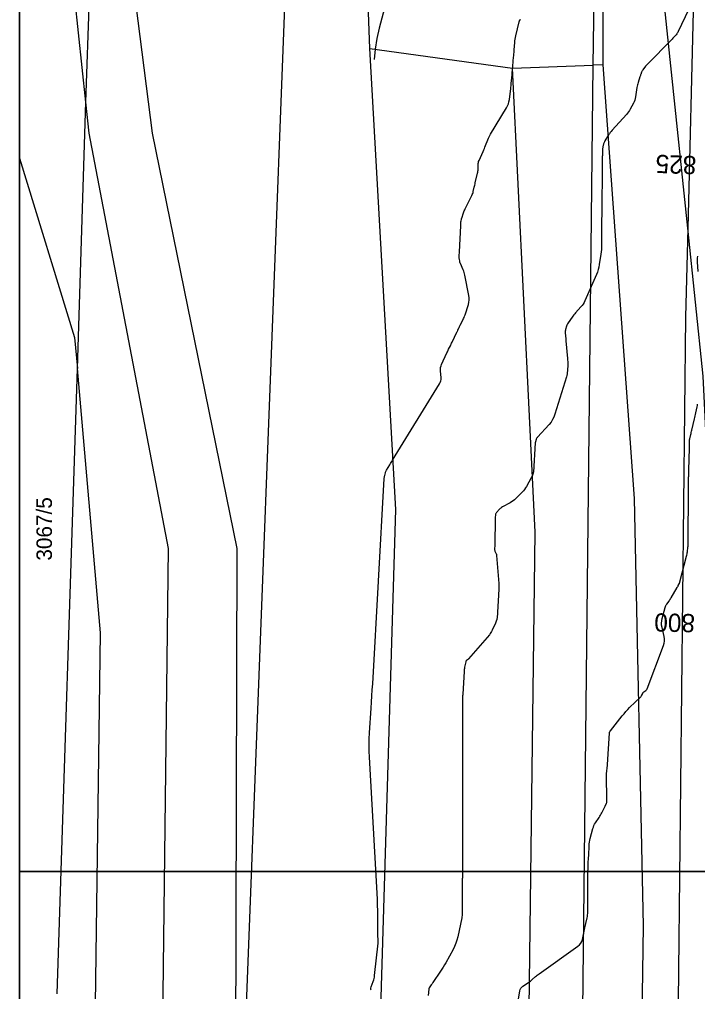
# Model space of a CAD drawing. Extents: x -534410 to -534262, y -1190162 to -1189584.
# Drawn here: x -534410.1 to -534373, y -1189801 to -1189747.8 of the extents above; entities that cross this region are included whole.
import ezdxf

# ---------------------------------------------------------------- set-up
doc = ezdxf.new("R2010")
doc.units = 0
for name, color, linetype in [('30', 7, 'Continuous'), ('31', 7, 'Continuous'), ('_N_text', 7, 'Continuous'), ('_rámeček', 7, 'Continuous'), ('_rámeček_mřížka', 7, 'Continuous'), ('Hranice parcel', 7, 'Continuous'), ('Parcelní čísla', 7, 'Continuous')]:
    doc.layers.add(name, color=color, linetype=linetype)

msp = doc.modelspace()

# ---------------------------------------------------------------- linework, layer by layer
at = {"layer": '30'}
for points in [[(-534389.675, -1189745.496), (-534390.401, -1189748.249), (-534390.532, -1189748.817), (-534390.627, -1189749.39), (-534390.685, -1189749.968)], [(-534373.458, -1189747.24), (-534374.015, -1189748.431), (-534374.04, -1189748.478), (-534374.067, -1189748.523), (-534374.097, -1189748.566), (-534374.131, -1189748.607), (-534374.272, -1189748.765), (-534374.307, -1189748.805), (-534374.343, -1189748.843), (-534374.38, -1189748.882), (-534374.417, -1189748.92), (-534375.669, -1189750.182), (-534375.706, -1189750.219), (-534375.741, -1189750.258), (-534375.775, -1189750.298), (-534375.807, -1189750.339), (-534375.958, -1189750.534), (-534375.978, -1189750.562), (-534375.995, -1189750.591), (-534376.01, -1189750.621), (-534376.023, -1189750.652), (-534376.068, -1189750.78), (-534376.08, -1189750.812), (-534376.091, -1189750.845), (-534376.102, -1189750.877), (-534376.112, -1189750.909), (-534376.216, -1189751.231), (-534376.236, -1189751.295), (-534376.253, -1189751.36), (-534376.267, -1189751.426), (-534376.278, -1189751.493), (-534376.359, -1189752.02), (-534376.376, -1189752.11), (-534376.401, -1189752.196), (-534376.434, -1189752.28), (-534376.474, -1189752.362), (-534376.648, -1189752.684), (-534376.694, -1189752.763), (-534376.744, -1189752.838), (-534376.799, -1189752.911), (-534376.858, -1189752.98), (-534377.636, -1189753.843), (-534377.688, -1189753.904), (-534377.738, -1189753.966), (-534377.784, -1189754.031), (-534377.828, -1189754.098), (-534378.037, -1189754.431), (-534378.058, -1189754.468), (-534378.076, -1189754.507), (-534378.091, -1189754.548), (-534378.103, -1189754.59), (-534378.144, -1189754.76), (-534378.153, -1189754.802), (-534378.159, -1189754.845), (-534378.164, -1189754.888), (-534378.166, -1189754.932), (-534378.172, -1189755.169), (-534378.174, -1189755.223), (-534378.175, -1189755.277), (-534378.175, -1189755.331), (-534378.175, -1189755.385), (-534378.175, -1189756.304), (-534378.175, -1189756.358), (-534378.176, -1189756.412), (-534378.177, -1189756.466), (-534378.178, -1189756.52), (-534378.184, -1189756.736), (-534378.186, -1189756.79), (-534378.187, -1189756.844), (-534378.189, -1189756.899), (-534378.191, -1189756.953), (-534378.198, -1189757.188), (-534378.2, -1189757.246), (-534378.201, -1189757.303), (-534378.201, -1189757.36), (-534378.202, -1189757.418), (-534378.202, -1189758.271), (-534378.202, -1189758.329), (-534378.203, -1189758.386), (-534378.204, -1189758.443), (-534378.206, -1189758.501), (-534378.213, -1189758.73), (-534378.215, -1189758.787), (-534378.216, -1189758.845), (-534378.217, -1189758.902), (-534378.217, -1189758.959), (-534378.217, -1189760.107), (-534378.22, -1189760.239), (-534378.227, -1189760.37), (-534378.239, -1189760.5), (-534378.256, -1189760.63), (-534378.342, -1189761.207), (-534378.368, -1189761.345), (-534378.402, -1189761.48), (-534378.445, -1189761.613), (-534378.497, -1189761.744), (-534379.132, -1189763.195), (-534379.175, -1189763.284), (-534379.224, -1189763.368), (-534379.281, -1189763.448), (-534379.344, -1189763.523), (-534379.637, -1189763.846), (-534379.689, -1189763.905), (-534379.739, -1189763.966), (-534379.788, -1189764.028), (-534379.834, -1189764.092), (-534380.052, -1189764.403), (-534380.078, -1189764.442), (-534380.1, -1189764.484), (-534380.119, -1189764.527), (-534380.135, -1189764.572), (-534380.19, -1189764.754), (-534380.201, -1189764.799), (-534380.208, -1189764.845), (-534380.211, -1189764.892), (-534380.209, -1189764.939), (-534380.179, -1189765.28), (-534380.169, -1189765.389), (-534380.083, -1189766.351), (-534380.077, -1189766.435), (-534380.073, -1189766.52), (-534380.073, -1189766.604), (-534380.074, -1189766.688), (-534380.087, -1189767.026), (-534380.093, -1189767.11), (-534380.104, -1189767.193), (-534380.121, -1189767.275), (-534380.143, -1189767.357), (-534380.773, -1189769.408), (-534380.829, -1189769.559), (-534380.899, -1189769.701), (-534380.986, -1189769.835), (-534381.087, -1189769.959), (-534381.723, -1189770.659), (-534381.733, -1189770.67), (-534381.742, -1189770.682), (-534381.751, -1189770.694), (-534381.759, -1189770.706), (-534381.797, -1189770.768), (-534381.801, -1189770.775), (-534381.805, -1189770.782), (-534381.808, -1189770.789), (-534381.81, -1189770.797), (-534381.819, -1189770.837), (-534381.825, -1189770.86), (-534381.841, -1189770.923), (-534381.845, -1189770.937), (-534381.847, -1189770.95), (-534381.849, -1189770.963), (-534381.85, -1189770.977), (-534381.954, -1189772.572), (-534381.957, -1189772.6), (-534381.963, -1189772.629), (-534381.971, -1189772.656), (-534381.981, -1189772.684), (-534382.028, -1189772.791), (-534382.04, -1189772.818), (-534382.052, -1189772.844), (-534382.065, -1189772.87), (-534382.079, -1189772.896), (-534382.335, -1189773.359), (-534382.385, -1189773.443), (-534382.44, -1189773.522), (-534382.501, -1189773.598), (-534382.568, -1189773.669), (-534382.918, -1189774.02), (-534382.99, -1189774.086), (-534383.065, -1189774.147), (-534383.145, -1189774.203), (-534383.228, -1189774.253), (-534383.651, -1189774.486), (-534383.696, -1189774.513), (-534383.738, -1189774.543), (-534383.777, -1189774.577), (-534383.814, -1189774.613), (-534383.975, -1189774.789), (-534383.998, -1189774.818), (-534384.015, -1189774.849), (-534384.026, -1189774.883), (-534384.031, -1189774.92), (-534384.04, -1189775.071), (-534384.042, -1189775.108), (-534384.044, -1189775.146), (-534384.045, -1189775.184), (-534384.046, -1189775.222), (-534384.063, -1189776.443), (-534384.064, -1189776.483), (-534384.065, -1189776.523), (-534384.067, -1189776.563), (-534384.07, -1189776.604), (-534384.082, -1189776.78), (-534384.082, -1189776.812), (-534384.078, -1189776.843), (-534384.07, -1189776.873), (-534384.059, -1189776.903), (-534384.005, -1189777.02), (-534383.992, -1189777.05), (-534383.983, -1189777.08), (-534383.976, -1189777.111), (-534383.972, -1189777.143), (-534383.854, -1189778.685), (-534383.853, -1189778.711), (-534383.851, -1189778.737), (-534383.85, -1189778.763), (-534383.849, -1189778.789), (-534383.846, -1189778.894), (-534383.846, -1189778.92), (-534383.846, -1189778.946), (-534383.847, -1189778.973), (-534383.848, -1189778.999), (-534383.948, -1189780.581), (-534383.951, -1189780.608), (-534383.955, -1189780.635), (-534383.962, -1189780.662), (-534383.97, -1189780.688), (-534384.008, -1189780.792), (-534384.017, -1189780.818), (-534384.027, -1189780.844), (-534384.038, -1189780.869), (-534384.05, -1189780.895), (-534384.211, -1189781.242), (-534384.244, -1189781.307), (-534384.281, -1189781.369), (-534384.323, -1189781.428), (-534384.368, -1189781.485), (-534385.516, -1189782.817), (-534385.528, -1189782.83), (-534385.541, -1189782.843), (-534385.555, -1189782.855), (-534385.569, -1189782.866), (-534385.628, -1189782.908), (-534385.642, -1189782.92), (-534385.652, -1189782.933), (-534385.66, -1189782.949), (-534385.664, -1189782.966), (-534385.722, -1189783.273), (-534385.731, -1189783.33), (-534385.739, -1189783.387), (-534385.745, -1189783.445), (-534385.749, -1189783.503), (-534385.815, -1189784.752), (-534385.816, -1189784.762), (-534385.817, -1189784.771), (-534385.819, -1189784.78), (-534385.822, -1189784.79), (-534385.832, -1189784.826), (-534385.834, -1189784.835), (-534385.836, -1189784.845), (-534385.837, -1189784.854), (-534385.837, -1189784.864), (-534385.837, -1189790.82), (-534385.837, -1189790.844), (-534385.838, -1189790.869), (-534385.839, -1189790.917), (-534385.84, -1189790.941), (-534385.84, -1189790.965), (-534385.84, -1189792.724), (-534385.84, -1189792.748), (-534385.84, -1189792.772), (-534385.842, -1189792.832), (-534385.843, -1189792.869), (-534385.845, -1189792.921), (-534385.845, -1189792.934), (-534385.845, -1189792.947), (-534385.846, -1189792.96), (-534385.846, -1189792.973), (-534385.846, -1189794.716), (-534385.846, -1189794.729), (-534385.846, -1189794.742), (-534385.846, -1189794.755), (-534385.846, -1189794.768), (-534385.848, -1189794.819), (-534385.849, -1189794.832), (-534385.849, -1189794.845), (-534385.849, -1189794.857), (-534385.849, -1189794.87), (-534385.849, -1189796.811), (-534385.85, -1189796.828), (-534385.851, -1189796.844), (-534385.853, -1189796.861), (-534385.856, -1189796.878), (-534385.869, -1189796.944), (-534385.876, -1189796.977), (-534385.882, -1189797.01), (-534386.104, -1189798.05), (-534386.148, -1189798.226), (-534386.205, -1189798.398), (-534386.274, -1189798.566), (-534386.355, -1189798.728), (-534386.753, -1189799.461), (-534386.821, -1189799.581), (-534386.891, -1189799.699), (-534386.964, -1189799.815), (-534387.041, -1189799.93), (-534387.468, -1189800.551), (-534387.489, -1189800.581), (-534387.509, -1189800.61), (-534387.529, -1189800.639), (-534387.549, -1189800.669), (-534387.663, -1189800.833), (-534387.667, -1189800.839), (-534387.67, -1189800.845), (-534387.673, -1189800.851), (-534387.676, -1189800.858), (-534387.685, -1189800.885), (-534387.687, -1189800.892), (-534387.688, -1189800.899), (-534387.69, -1189800.906), (-534387.691, -1189800.913), (-534387.73, -1189801.248)]]:
    msp.add_lwpolyline(points, dxfattribs=at)
at = {"layer": '31'}
for points in [[(-534390.843, -1189800.964), (-534390.857, -1189800.933), (-534390.862, -1189800.864), (-534390.845, -1189800.79), (-534390.732, -1189800.482), (-534390.706, -1189800.404), (-534390.685, -1189800.325), (-534390.669, -1189800.245), (-534390.657, -1189800.164), (-534390.465, -1189798.386), (-534390.461, -1189798.337), (-534390.459, -1189798.287), (-534390.459, -1189798.238), (-534390.462, -1189798.188), (-534390.477, -1189797.99), (-534390.48, -1189797.941), (-534390.483, -1189797.891), (-534390.484, -1189797.842), (-534390.484, -1189797.792), (-534390.484, -1189796.747), (-534390.486, -1189796.556), (-534390.49, -1189796.365), (-534390.496, -1189796.175), (-534390.506, -1189795.984), (-534390.938, -1189788.199), (-534390.952, -1189787.863), (-534390.956, -1189787.527), (-534390.949, -1189787.192), (-534390.932, -1189786.857), (-534390.845, -1189785.515), (-534390.823, -1189785.18), (-534390.803, -1189784.844), (-534390.783, -1189784.509), (-534390.763, -1189784.173), (-534390.128, -1189772.923), (-534390.125, -1189772.884), (-534390.12, -1189772.845), (-534390.113, -1189772.806), (-534390.105, -1189772.768), (-534390.068, -1189772.614), (-534390.058, -1189772.577), (-534390.044, -1189772.54), (-534390.028, -1189772.505), (-534390.008, -1189772.471), (-534389.82, -1189772.172), (-534389.782, -1189772.111), (-534389.743, -1189772.049), (-534389.705, -1189771.988), (-534389.668, -1189771.927), (-534387.099, -1189767.745), (-534387.057, -1189767.664), (-534387.029, -1189767.58), (-534387.016, -1189767.492), (-534387.016, -1189767.401), (-534387.046, -1189767.03), (-534387.047, -1189766.938), (-534387.037, -1189766.849), (-534387.016, -1189766.761), (-534386.982, -1189766.676), (-534386.689, -1189766.04), (-534386.667, -1189765.992), (-534386.644, -1189765.943), (-534386.621, -1189765.895), (-534386.598, -1189765.847), (-534386.504, -1189765.655), (-534386.481, -1189765.607), (-534386.457, -1189765.559), (-534386.434, -1189765.51), (-534386.411, -1189765.462), (-534386.146, -1189764.908), (-534386.131, -1189764.876), (-534386.116, -1189764.844), (-534386.101, -1189764.813), (-534386.086, -1189764.781), (-534386.026, -1189764.654), (-534386.011, -1189764.623), (-534385.996, -1189764.591), (-534385.98, -1189764.56), (-534385.965, -1189764.529), (-534385.806, -1189764.22), (-534385.776, -1189764.158), (-534385.748, -1189764.095), (-534385.723, -1189764.03), (-534385.701, -1189763.965), (-534385.515, -1189763.385), (-534385.485, -1189763.266), (-534385.471, -1189763.146), (-534385.472, -1189763.025), (-534385.489, -1189762.904), (-534385.714, -1189761.781), (-534385.73, -1189761.708), (-534385.751, -1189761.636), (-534385.775, -1189761.565), (-534385.802, -1189761.496), (-534385.956, -1189761.137), (-534385.967, -1189761.109), (-534385.977, -1189761.081), (-534385.985, -1189761.052), (-534385.991, -1189761.022), (-534386.012, -1189760.904), (-534386.016, -1189760.874), (-534386.019, -1189760.844), (-534386.02, -1189760.814), (-534386.019, -1189760.784), (-534386.013, -1189760.645), (-534386.009, -1189760.578), (-534386.006, -1189760.512), (-534385.935, -1189759.081), (-534385.931, -1189759.01), (-534385.925, -1189758.883), (-534385.924, -1189758.864), (-534385.922, -1189758.845), (-534385.92, -1189758.825), (-534385.917, -1189758.806), (-534385.903, -1189758.729), (-534385.9, -1189758.71), (-534385.895, -1189758.691), (-534385.89, -1189758.672), (-534385.884, -1189758.654), (-534385.782, -1189758.363), (-534385.761, -1189758.309), (-534385.74, -1189758.255), (-534385.716, -1189758.202), (-534385.691, -1189758.15), (-534385.327, -1189757.422), (-534385.302, -1189757.368), (-534385.28, -1189757.312), (-534385.261, -1189757.255), (-534385.246, -1189757.197), (-534385.192, -1189756.962), (-534385.178, -1189756.903), (-534385.165, -1189756.845), (-534385.151, -1189756.786), (-534385.137, -1189756.727), (-534385.011, -1189756.202), (-534384.999, -1189756.143), (-534384.99, -1189756.084), (-534384.985, -1189756.025), (-534384.984, -1189755.965), (-534384.984, -1189755.724), (-534384.98, -1189755.665), (-534384.971, -1189755.607), (-534384.955, -1189755.55), (-534384.934, -1189755.495), (-534384.708, -1189755.001), (-534384.673, -1189754.923), (-534384.639, -1189754.844), (-534384.606, -1189754.764), (-534384.574, -1189754.684), (-534384.448, -1189754.363), (-534384.415, -1189754.284), (-534384.378, -1189754.206), (-534384.339, -1189754.13), (-534384.296, -1189754.055), (-534383.43, -1189752.617), (-534383.372, -1189752.508), (-534383.326, -1189752.394), (-534383.292, -1189752.277), (-534383.27, -1189752.155), (-534383.194, -1189751.553), (-534383.185, -1189751.482), (-534383.177, -1189751.411), (-534383.17, -1189751.341), (-534383.163, -1189751.27), (-534383.137, -1189750.986), (-534383.131, -1189750.915), (-534383.125, -1189750.844), (-534383.119, -1189750.774), (-534383.113, -1189750.703), (-534383.084, -1189750.323), (-534383.078, -1189750.248), (-534383.071, -1189750.174), (-534383.064, -1189750.099), (-534383.057, -1189750.024), (-534383.026, -1189749.726), (-534383.019, -1189749.651), (-534383.012, -1189749.577), (-534383.006, -1189749.502), (-534383, -1189749.427), (-534382.97, -1189749.028), (-534382.962, -1189748.936), (-534382.949, -1189748.846), (-534382.933, -1189748.755), (-534382.914, -1189748.666), (-534382.73, -1189747.896), (-534382.726, -1189747.88), (-534382.721, -1189747.866), (-534382.714, -1189747.851), (-534382.706, -1189747.838), (-534382.672, -1189747.784), (-534382.664, -1189747.77)], [(-534372.918, -1189761.59), (-534372.955, -1189761.052), (-534372.959, -1189760.948), (-534372.957, -1189760.845), (-534372.948, -1189760.742)], [(-534382.813, -1189801.684), (-534382.694, -1189801.008), (-534382.673, -1189800.931), (-534382.638, -1189800.862), (-534382.59, -1189800.802), (-534382.528, -1189800.751), (-534382.22, -1189800.54), (-534382.169, -1189800.505), (-534382.12, -1189800.467), (-534382.071, -1189800.428), (-534382.024, -1189800.388), (-534381.837, -1189800.224), (-534381.789, -1189800.184), (-534381.741, -1189800.145), (-534381.692, -1189800.107), (-534381.642, -1189800.07), (-534379.515, -1189798.56), (-534379.426, -1189798.484), (-534379.355, -1189798.396), (-534379.302, -1189798.296), (-534379.267, -1189798.184), (-534379.13, -1189797.554), (-534379.078, -1189797.317), (-534379.01, -1189797.002), (-534378.995, -1189796.923), (-534378.984, -1189796.844), (-534378.977, -1189796.764), (-534378.975, -1189796.683), (-534378.975, -1189795.036), (-534378.975, -1189794.94), (-534378.974, -1189794.845), (-534378.972, -1189794.749), (-534378.969, -1189794.653), (-534378.951, -1189794.146), (-534378.95, -1189794.098), (-534378.947, -1189794.05), (-534378.945, -1189794.002), (-534378.942, -1189793.953), (-534378.929, -1189793.761), (-534378.926, -1189793.713), (-534378.924, -1189793.665), (-534378.921, -1189793.617), (-534378.92, -1189793.569), (-534378.903, -1189793.05), (-534378.897, -1189792.948), (-534378.884, -1189792.846), (-534378.866, -1189792.746), (-534378.841, -1189792.647), (-534378.69, -1189792.107), (-534378.664, -1189792.026), (-534378.633, -1189791.949), (-534378.595, -1189791.874), (-534378.552, -1189791.801), (-534378.355, -1189791.499), (-534378.315, -1189791.437), (-534378.277, -1189791.373), (-534378.24, -1189791.308), (-534378.206, -1189791.242), (-534378.025, -1189790.888), (-534378.014, -1189790.866), (-534378.003, -1189790.844), (-534377.993, -1189790.822), (-534377.983, -1189790.8), (-534377.942, -1189790.71), (-534377.934, -1189790.687), (-534377.927, -1189790.664), (-534377.924, -1189790.64), (-534377.923, -1189790.616), (-534377.942, -1189789.134), (-534377.942, -1189789.089), (-534377.94, -1189789.044), (-534377.936, -1189789), (-534377.931, -1189788.956), (-534377.909, -1189788.779), (-534377.903, -1189788.735), (-534377.899, -1189788.69), (-534377.895, -1189788.646), (-534377.891, -1189788.601), (-534377.78, -1189786.89), (-534377.78, -1189786.881), (-534377.779, -1189786.872), (-534377.78, -1189786.852), (-534377.779, -1189786.845), (-534377.778, -1189786.837), (-534377.774, -1189786.823), (-534377.771, -1189786.816), (-534377.768, -1189786.81), (-534377.75, -1189786.78), (-534377.747, -1189786.774), (-534377.743, -1189786.768), (-534377.739, -1189786.762), (-534377.734, -1189786.757), (-534377.08, -1189785.932), (-534376.984, -1189785.815), (-534376.885, -1189785.702), (-534376.783, -1189785.591), (-534376.677, -1189785.483), (-534376.071, -1189784.882), (-534376.053, -1189784.863), (-534376.036, -1189784.842), (-534376.022, -1189784.82), (-534376.009, -1189784.796), (-534375.96, -1189784.7), (-534375.947, -1189784.677), (-534375.931, -1189784.656), (-534375.913, -1189784.637), (-534375.892, -1189784.62), (-534375.791, -1189784.549), (-534375.769, -1189784.531), (-534375.75, -1189784.51), (-534375.734, -1189784.486), (-534375.722, -1189784.46), (-534374.823, -1189782.072), (-534374.787, -1189781.953), (-534374.77, -1189781.832), (-534374.77, -1189781.71), (-534374.789, -1189781.587), (-534374.903, -1189781.086), (-534374.923, -1189780.965), (-534374.928, -1189780.845), (-534374.918, -1189780.725), (-534374.893, -1189780.605), (-534374.726, -1189779.988), (-534374.711, -1189779.939), (-534374.691, -1189779.892), (-534374.667, -1189779.848), (-534374.638, -1189779.805), (-534374.516, -1189779.639), (-534374.486, -1189779.597), (-534374.457, -1189779.554), (-534374.429, -1189779.511), (-534374.402, -1189779.467), (-534374.066, -1189778.892), (-534374.052, -1189778.868), (-534374.039, -1189778.844), (-534374.026, -1189778.82), (-534374.014, -1189778.795), (-534373.964, -1189778.697), (-534373.953, -1189778.672), (-534373.943, -1189778.647), (-534373.934, -1189778.621), (-534373.926, -1189778.594), (-534373.557, -1189777.182), (-534373.543, -1189777.122), (-534373.53, -1189777.061), (-534373.52, -1189777), (-534373.511, -1189776.939), (-534373.482, -1189776.692), (-534373.476, -1189776.631), (-534373.472, -1189776.569), (-534373.469, -1189776.507), (-534373.468, -1189776.445), (-534373.468, -1189775.189), (-534373.468, -1189775.154), (-534373.466, -1189775.12), (-534373.465, -1189775.085), (-534373.462, -1189775.051), (-534373.45, -1189774.913), (-534373.447, -1189774.879), (-534373.445, -1189774.844), (-534373.444, -1189774.81), (-534373.444, -1189774.775), (-534373.443, -1189774.619), (-534373.443, -1189774.582), (-534373.443, -1189774.544), (-534373.443, -1189774.507), (-534373.443, -1189774.469), (-534373.443, -1189773.22), (-534373.443, -1189773.145), (-534373.443, -1189773.07), (-534373.442, -1189772.92), (-534373.442, -1189772.882), (-534373.442, -1189772.845), (-534373.441, -1189772.807), (-534373.441, -1189772.769), (-534373.439, -1189772.615), (-534373.438, -1189772.577), (-534373.437, -1189772.539), (-534373.436, -1189772.5), (-534373.435, -1189772.462), (-534373.404, -1189771.271), (-534373.403, -1189771.228), (-534373.402, -1189771.185), (-534373.402, -1189771.143), (-534373.401, -1189771.1), (-534373.398, -1189770.93), (-534373.397, -1189770.887), (-534373.393, -1189770.845), (-534373.387, -1189770.803), (-534373.378, -1189770.761), (-534373.321, -1189770.509), (-534373.309, -1189770.453), (-534373.296, -1189770.397), (-534373.283, -1189770.341), (-534373.271, -1189770.286), (-534373.13, -1189769.657), (-534373.112, -1189769.575), (-534373.093, -1189769.494), (-534373.075, -1189769.413), (-534373.057, -1189769.332), (-534372.983, -1189769.007), (-534372.965, -1189768.926), (-534372.949, -1189768.844)]]:
    msp.add_lwpolyline(points, dxfattribs=at)
at = {"layer": '_rámeček'}
msp.add_line((-534410.126, -1189584.47), (-534410.126, -1190161.97), dxfattribs=at)
for points in [[(-534410.126, -1189689.47), (-534261.626, -1189689.47), (-534261.626, -1189794.47), (-534410.126, -1189794.47)], [(-534410.126, -1189794.47), (-534261.626, -1189794.47), (-534261.626, -1189899.47), (-534410.126, -1189899.47)]]:
    msp.add_lwpolyline(points, close=True, dxfattribs=at)
at = {"layer": '_rámeček_mřížka'}
for p, q in [((-534410.126, -1189584.47), (-534410.126, -1190161.97)), ((-534407.126, -1189794.47), (-534410.126, -1189794.47))]:
    msp.add_line(p, q, dxfattribs=at)
at = {"layer": 'Hranice parcel'}
for p, q in [((-534371.04, -1189658.4), (-534373.49, -1189759.21)), ((-534378.67, -1189750.28), (-534377.8, -1189671.05)), ((-534406.48, -1189752.31), (-534404.82, -1189701)), ((-534398.3, -1189817.87), (-534394.19, -1189710.57)), ((-534390.92, -1189749.37), (-534383.09, -1189750.44)), ((-534383.09, -1189750.44), (-534378.67, -1189750.28)), ((-534378.12, -1189750.26), (-534378.67, -1189750.28)), ((-534406.95, -1189766.9), (-534406.48, -1189752.31)), ((-534373.49, -1189759.21), (-534373.61, -1189764.09)), ((-534408.06, -1189801.17), (-534406.95, -1189766.9))]:
    msp.add_line(p, q, dxfattribs=at)
for points in [[(-534373.49, -1189759.21), (-534375.27, -1189742.09), (-534373.87, -1189702.99), (-534373.87, -1189662.03), (-534374.42, -1189646.7)], [(-534378.12, -1189750.26), (-534378.12, -1189746.17), (-534376.49, -1189693.82), (-534377.8, -1189671.05)], [(-534406.48, -1189752.31), (-534408.29, -1189735.19), (-534406.08, -1189700.59)], [(-534398.3, -1189817.87), (-534398.2, -1189776.76), (-534402.83, -1189754), (-534404.51, -1189740.82), (-534402.1, -1189701.89)], [(-534390.92, -1189749.37), (-534391.09, -1189744.93), (-534393.26, -1189731.27), (-534393.26, -1189715.05), (-534394.19, -1189710.57)], [(-534395.93, -1189955.06), (-534393.76, -1189916.2), (-534389.49, -1189774.63), (-534390.92, -1189749.37)], [(-534385.61, -1189919.11), (-534380.06, -1189877.29), (-534378.67, -1189750.28)], [(-534383.94, -1189956.8), (-534379.19, -1189918.48), (-534376.74, -1189853.94), (-534375.92, -1189797.44), (-534376.41, -1189774.02), (-534378.12, -1189750.26)], [(-534385.61, -1189919.11), (-534383.81, -1189892.54), (-534382.22, -1189804.86), (-534381.85, -1189775.86), (-534383.09, -1189750.44)], [(-534406.13, -1189942), (-534403.45, -1189886.77), (-534402.68, -1189837.82), (-534401.95, -1189776.76), (-534406.3, -1189754), (-534406.48, -1189752.31)], [(-534410.126, -1189755.374), (-534407.1, -1189765.2), (-534406.95, -1189766.9)], [(-534369.38, -1189820.8), (-534370.35, -1189813.98), (-534372.65, -1189767.31), (-534373.49, -1189759.21)], [(-534373.61, -1189764.09), (-534375.04, -1189897.07), (-534384.28, -1189963.65)], [(-534410.126, -1189932.794), (-534408.16, -1189899.66), (-534406.57, -1189847.9), (-534405.68, -1189781.38), (-534406.95, -1189766.9)]]:
    msp.add_lwpolyline(points, dxfattribs=at)

# ---------------------------------------------------------------- texts
at = {"layer": '_N_text'}
for s, rotation, p in [('825', 177.8451, (-534373.004, -1189755.263)), ('800', 178.6463, (-534373.082, -1189780.36))]:
    msp.add_text(s, height=1, rotation=rotation, dxfattribs=at).set_placement(p)
at = {"layer": 'Parcelní čísla'}
msp.add_text('3067/5', height=0.85, rotation=90, dxfattribs=at).set_placement((-534408.344, -1189777.427))

doc.saveas('drawing.dxf')
